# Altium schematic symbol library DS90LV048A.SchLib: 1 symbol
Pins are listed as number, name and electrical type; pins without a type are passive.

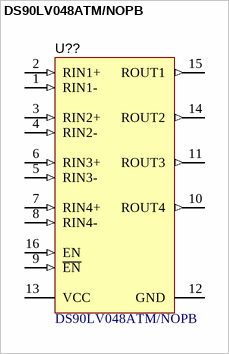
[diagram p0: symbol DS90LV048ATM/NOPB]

## DS90LV048ATM/NOPB
designator U??
3V LVDS Quad CMOS Differential Line Receiver, 16-pin Narrow SOIC, Pb-Free; Manufacturer: Texas Instruments; PackageTopMarking: NS2ZXYTTE#*DS90LV048A*TM; PowerWise: N; CompType: Interface IC
footprint M16A_N (SOIC, 16-Leads, Body 9.9x3.9mm, Pitch 1.27mm, IPC Medium Density)
footprint M16A_L (SOIC, 16-Leads, Body 9.9x3.9mm, Pitch 1.27mm, IPC High Density)
footprint M16A_M (SOIC, 16-Leads, Body 9.9x3.9mm, Pitch 1.27mm, IPC Low Density)
pins: 1 RIN1- (in), 2 RIN1+ (in), 3 RIN2+ (in), 4 RIN2- (in), 5 RIN3- (in), 6 RIN3+ (in), 7 RIN4+ (in), 8 RIN4- (in), 9 ~{EN} (in), 10 ROUT4 (out), 11 ROUT3 (out), 12 GND (power), 13 VCC (power), 14 ROUT2 (out), 15 ROUT1 (out), 16 EN (in)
